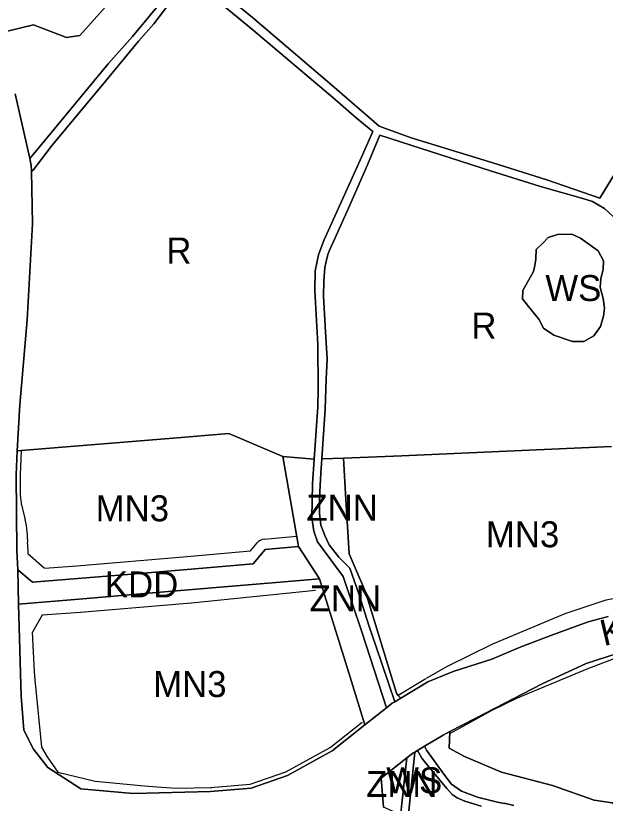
# Model space of a CAD drawing. Extents: x 7417187 to 7419415, y 5539178 to 5540826.
# Drawn here: x 7418228.7 to 7418455.5, y 5539930.4 to 5540233.3 of the extents above; entities that cross this region are included whole.
import ezdxf

# ---------------------------------------------------------------- set-up
doc = ezdxf.new("R2010")
doc.units = 0
for name, color, linetype in [('linie_rozgraniczajace', 7, 'Continuous'), ('linie_zabudowy_nieprzekraczalne', 7, 'Continuous'), ('oznaczenia_przeznaczen', 7, 'Continuous')]:
    doc.layers.add(name, color=color, linetype=linetype)

msp = doc.modelspace()

# ---------------------------------------------------------------- linework, layer by layer
at = {"layer": 'linie_rozgraniczajace'}
for p, q in [((7418228.49, 5540203.2), (7418234.02, 5540178.42)), ((7418234.02, 5540178.42), (7418234.62, 5540175.72)), ((7418234.62, 5540175.72), (7418234.67, 5540173.44)), ((7418234.67, 5540173.44), (7418235.17, 5540153.27)), ((7418235.17, 5540153.27), (7418233, 5540116.38)), ((7418233, 5540116.38), (7418230.22, 5540083.58)), ((7418230.22, 5540083.58), (7418229.26, 5540065.97)), ((7418229.26, 5540065.97), (7418228.84, 5540056.72)), ((7418228.84, 5540056.72), (7418229.08, 5540027.66)), ((7418229.08, 5540027.66), (7418229.44, 5540020.18)), ((7418229.44, 5540020.18), (7418229.69, 5540006.93)), ((7418229.69, 5540006.93), (7418230.69, 5539971.57)), ((7418448.84, 5540000.15), (7418456.65, 5540002.24)), ((7418434.59, 5539994.9), (7418448.84, 5540000.15)), ((7418422.7, 5539990.44), (7418434.59, 5539994.9)), ((7418411.84, 5539985.76), (7418422.7, 5539990.44)), ((7418396.96, 5539981.06), (7418411.84, 5539985.76)), ((7418460.09, 5539988), (7418448.1, 5539984.08)), ((7418448.1, 5539984.08), (7418431.16, 5539976.28)), ((7418387.18, 5539977.07), (7418396.96, 5539981.06)), ((7418376.77, 5539970.78), (7418387.18, 5539977.07)), ((7418431.16, 5539976.28), (7418405.44, 5539962.93)), ((7418230.69, 5539971.57), (7418231.83, 5539958.48)), ((7418374.56, 5539969.44), (7418376.77, 5539970.78)), ((7418362.93, 5539960.5), (7418371.35, 5539967.11)), ((7418371.35, 5539967.11), (7418373.55, 5539968.83)), ((7418373.55, 5539968.83), (7418374.56, 5539969.44)), ((7418405.44, 5539962.93), (7418395.62, 5539957.92)), ((7418231.83, 5539958.48), (7418235.49, 5539951.16)), ((7418350.41, 5539950.6), (7418362.93, 5539960.5)), ((7418395.62, 5539957.92), (7418393.1, 5539956.63)), ((7418393.1, 5539956.63), (7418385.93, 5539952.31)), ((7418385.93, 5539952.31), (7418383.29, 5539950.72)), ((7418235.49, 5539951.16), (7418241, 5539944.1)), ((7418333.18, 5539941.09), (7418350.41, 5539950.6)), ((7418381.45, 5539949.61), (7418379.12, 5539947.79)), ((7418382.19, 5539950.06), (7418381.45, 5539949.61)), ((7418383.29, 5539950.72), (7418382.19, 5539950.06)), ((7418379.12, 5539947.79), (7418369.25, 5539940)), ((7418241, 5539944.1), (7418253.73, 5539935.92)), ((7418319.22, 5539936.23), (7418333.18, 5539941.09)), ((7418369.25, 5539940), (7418370.12, 5539928.88)), ((7418253.73, 5539935.92), (7418270.91, 5539934.38)), ((7418270.91, 5539934.38), (7418274.03, 5539934.13)), ((7418274.03, 5539934.13), (7418303.62, 5539934.92)), ((7418303.62, 5539934.92), (7418319.22, 5539936.23))]:
    msp.add_line(p, q, dxfattribs=at)
for points in [[(7418227.82, 5540375.89), (7418237.98, 5540364.53), (7418262.36, 5540337.71), (7418286.86, 5540308.94), (7418290.2, 5540303.57), (7418291.35, 5540297.94), (7418292.32, 5540288.2), (7418294.69, 5540263.29), (7418294.79, 5540258.48), (7418294.26, 5540253.21), (7418292.47, 5540248.17), (7418273.58, 5540225.24), (7418264.17, 5540214.76), (7418235.51, 5540179.98), (7418234.02, 5540178.42), (7418228.49, 5540203.2)], [(7418226.81, 5540354.53), (7418253.06, 5540326.64), (7418254.07, 5540325.33), (7418267.85, 5540328.83), (7418275.05, 5540320.34), (7418284.84, 5540308.55), (7418288.35, 5540302.97), (7418275.62, 5540298.87), (7418279.2, 5540268.07), (7418279.82, 5540259.72), (7418279.51, 5540256.5), (7418279.22, 5540255.67), (7418269.71, 5540244.08), (7418253.27, 5540225.63), (7418248.19, 5540224.85), (7418235.5, 5540229.77), (7418221.14, 5540226.27)], [(7418221.14, 5540226.27), (7418235.5, 5540229.77), (7418248.19, 5540224.85), (7418253.27, 5540225.63), (7418269.71, 5540244.08), (7418279.22, 5540255.67), (7418279.51, 5540256.5), (7418279.82, 5540259.72), (7418279.2, 5540268.07), (7418275.62, 5540298.87), (7418288.35, 5540302.97), (7418284.84, 5540308.55), (7418275.05, 5540320.34), (7418267.85, 5540328.83), (7418254.07, 5540325.33), (7418253.06, 5540326.64), (7418226.81, 5540354.53)], [(7418297.74, 5540250.66), (7418319.78, 5540232.65), (7418350.22, 5540206.58), (7418368.55, 5540190.85), (7418369.92, 5540190.23), (7418380.76, 5540186.27), (7418412.2, 5540176.64), (7418433.02, 5540170.19), (7418453.39, 5540163.14), (7418465.08, 5540182.22)], [(7418538.04, 5540238.68), (7418496.96, 5540232.44), (7418486.08, 5540230.79), (7418462.63, 5540227.22), (7418464.94, 5540202.93), (7418468.97, 5540186.98), (7418465.08, 5540182.22), (7418453.39, 5540163.14), (7418433.02, 5540170.19), (7418412.2, 5540176.64), (7418380.76, 5540186.27), (7418369.92, 5540190.23), (7418368.55, 5540190.85), (7418350.22, 5540206.58), (7418319.78, 5540232.65), (7418297.74, 5540250.66)], [(7418458.58, 5540156.01), (7418455.21, 5540159.2), (7418450.6, 5540161.81), (7418446.87, 5540163), (7418430.5, 5540167.61), (7418411.37, 5540173.59), (7418368.73, 5540187.37), (7418363.97, 5540175.93), (7418357.14, 5540160.36), (7418351.56, 5540147.88), (7418349.51, 5540143.31), (7418348.8, 5540141.49), (7418348.05, 5540138.76), (7418347.62, 5540136.49), (7418347.16, 5540131.17), (7418347.09, 5540125.54), (7418347.66, 5540113.93), (7418348.47, 5540101.29), (7418348.1, 5540093.49), (7418347.74, 5540081.95), (7418346.45, 5540062.85), (7418346.08, 5540057.3), (7418345.55, 5540047.91), (7418345.55, 5540041.94), (7418346.1, 5540037.3), (7418346.99, 5540035.05), (7418347.58, 5540033.34), (7418349.25, 5540029.81), (7418353.02, 5540024.98), (7418357.16, 5540020.82), (7418360.48, 5540011.32), (7418364.66, 5539998.35), (7418367.22, 5539990.87), (7418374.56, 5539969.44), (7418373.55, 5539968.83), (7418371.35, 5539967.11), (7418361.82, 5539996.35), (7418354.7, 5540017.59), (7418344.81, 5540030.93), (7418343.3, 5540035), (7418342.62, 5540040.28), (7418342.81, 5540053.21), (7418343.51, 5540062.78), (7418344.85, 5540082.84), (7418345.06, 5540089.46), (7418344.87, 5540106.81), (7418343.78, 5540127.65), (7418343.91, 5540135.1), (7418345.13, 5540141.33), (7418347.17, 5540146.8), (7418361.24, 5540177.74), (7418366.05, 5540188.76), (7418359.69, 5540194.03), (7418350.67, 5540201.83), (7418319.98, 5540227.67), (7418295.39, 5540248.09), (7418281.73, 5540230.16), (7418275.85, 5540223.46), (7418262.63, 5540207.43), (7418242.72, 5540183.54), (7418235.31, 5540173.91), (7418234.67, 5540173.44), (7418234.62, 5540175.72), (7418234.02, 5540178.42), (7418235.51, 5540179.98), (7418264.17, 5540214.76), (7418273.58, 5540225.24), (7418292.47, 5540248.17)], [(7418457.92, 5540067.55), (7418377.24, 5540064.07), (7418354.81, 5540063.05), (7418346.45, 5540062.85), (7418347.74, 5540081.95), (7418348.1, 5540093.49), (7418348.47, 5540101.29), (7418347.66, 5540113.93), (7418347.09, 5540125.54), (7418347.16, 5540131.17), (7418347.62, 5540136.49), (7418348.05, 5540138.76), (7418348.8, 5540141.49), (7418349.51, 5540143.31), (7418351.56, 5540147.88), (7418357.14, 5540160.36), (7418363.97, 5540175.93), (7418368.73, 5540187.37), (7418411.37, 5540173.59), (7418430.5, 5540167.61), (7418446.87, 5540163), (7418450.6, 5540161.81), (7418455.21, 5540159.2), (7418458.58, 5540156.01)], [(7418456.65, 5540002.24), (7418448.84, 5540000.15), (7418434.59, 5539994.9), (7418422.7, 5539990.44), (7418411.84, 5539985.76), (7418396.96, 5539981.06), (7418387.18, 5539977.07), (7418376.77, 5539970.78), (7418375.8, 5539971.82), (7418375.17, 5539972.74), (7418363.2, 5540011.65), (7418359.25, 5540020.93), (7418356.89, 5540026.36), (7418355.7, 5540047.26), (7418354.81, 5540063.05), (7418377.24, 5540064.07), (7418457.92, 5540067.55)], [(7418467.69, 5539924.67), (7418458.16, 5539930.52), (7418451.22, 5539931.57), (7418435.2, 5539937.16), (7418415.61, 5539942.33), (7418401.3, 5539948.39), (7418395.47, 5539951.6), (7418395.62, 5539957.92), (7418405.44, 5539962.93), (7418431.16, 5539976.28), (7418448.1, 5539984.08), (7418460.09, 5539988), (7418469.7, 5539989.61), (7418477.67, 5539989.67), (7418486.12, 5539988.52), (7418526.66, 5539977.12), (7418549.91, 5539970.51), (7418571.39, 5539965.86), (7418582.99, 5539964.37), (7418587.53, 5539958.72), (7418610.13, 5539947.65), (7418632.89, 5539933.88), (7418645.61, 5539926.63)], [(7418420.25, 5539929.52), (7418416.54, 5539930.38), (7418416.54, 5539930.27), (7418414.01, 5539930.78), (7418406.38, 5539932.75), (7418400.14, 5539935.02), (7418396.28, 5539937.71), (7418393.8, 5539941.09), (7418386.7, 5539950.77), (7418385.93, 5539952.31), (7418393.1, 5539956.63), (7418395.62, 5539957.92), (7418395.47, 5539951.6), (7418401.3, 5539948.39), (7418415.61, 5539942.33), (7418435.2, 5539937.16), (7418451.22, 5539931.57), (7418458.16, 5539930.52), (7418467.69, 5539924.67)], [(7418407.77, 5539929.32), (7418401.48, 5539931.12), (7418398.49, 5539932.48), (7418396.55, 5539933.79), (7418394.54, 5539936.06), (7418391.34, 5539939.93), (7418386.41, 5539945.78), (7418384.87, 5539947.74), (7418383.73, 5539949.71), (7418383.29, 5539950.72), (7418385.93, 5539952.31), (7418386.7, 5539950.77), (7418393.8, 5539941.09), (7418396.28, 5539937.71), (7418400.14, 5539935.02), (7418406.38, 5539932.75), (7418414.01, 5539930.78), (7418416.54, 5539930.27), (7418416.54, 5539930.38), (7418420.25, 5539929.52)], [(7418379.52, 5539923.81), (7418382.19, 5539950.06), (7418383.29, 5539950.72), (7418383.73, 5539949.71), (7418384.87, 5539947.74), (7418386.41, 5539945.78), (7418391.34, 5539939.93), (7418394.54, 5539936.06), (7418396.55, 5539933.79), (7418398.49, 5539932.48), (7418401.48, 5539931.12), (7418407.77, 5539929.32)]]:
    msp.add_lwpolyline(points, dxfattribs=at)
for points in [[(7418343.51, 5540062.78), (7418331.42, 5540063.8), (7418310.69, 5540072.54), (7418289.27, 5540070.81), (7418229.26, 5540065.97), (7418230.22, 5540083.58), (7418233, 5540116.38), (7418235.17, 5540153.27), (7418234.67, 5540173.44), (7418235.31, 5540173.91), (7418242.72, 5540183.54), (7418262.63, 5540207.43), (7418275.85, 5540223.46), (7418281.73, 5540230.16), (7418295.39, 5540248.09), (7418319.98, 5540227.67), (7418350.67, 5540201.83), (7418359.69, 5540194.03), (7418366.05, 5540188.76), (7418361.24, 5540177.74), (7418347.17, 5540146.8), (7418345.13, 5540141.33), (7418343.91, 5540135.1), (7418343.78, 5540127.65), (7418344.87, 5540106.81), (7418345.06, 5540089.46), (7418344.85, 5540082.84)], [(7418447.21, 5540108.04), (7418442.92, 5540108.01), (7418435.7, 5540110.43), (7418431.68, 5540113.13), (7418429.93, 5540116.58), (7418425.93, 5540121.5), (7418423.67, 5540124.41), (7418423.82, 5540127.61), (7418427.81, 5540134.85), (7418428.42, 5540137.24), (7418428.8, 5540139.59), (7418428.93, 5540143.36), (7418431.64, 5540145.9), (7418433.55, 5540147.98), (7418437.07, 5540149.17), (7418442.6, 5540149.21), (7418445.93, 5540147.67), (7418452.75, 5540142.8), (7418454.81, 5540138.99), (7418454.65, 5540135.84), (7418453.76, 5540132.05), (7418453.46, 5540128.85), (7418454.68, 5540124.58), (7418455.16, 5540120.83), (7418454.77, 5540117.72), (7418453.63, 5540113.79), (7418451.03, 5540110.11)], [(7418447.21, 5540108.04), (7418451.03, 5540110.11), (7418453.63, 5540113.79), (7418454.77, 5540117.72), (7418455.16, 5540120.83), (7418454.68, 5540124.58), (7418453.46, 5540128.85), (7418453.76, 5540132.05), (7418454.65, 5540135.84), (7418454.81, 5540138.99), (7418452.75, 5540142.8), (7418445.93, 5540147.67), (7418442.6, 5540149.21), (7418437.07, 5540149.17), (7418433.55, 5540147.98), (7418431.64, 5540145.9), (7418428.93, 5540143.36), (7418428.8, 5540139.59), (7418428.42, 5540137.24), (7418427.81, 5540134.85), (7418423.82, 5540127.61), (7418423.67, 5540124.41), (7418425.93, 5540121.5), (7418429.93, 5540116.58), (7418431.68, 5540113.13), (7418435.7, 5540110.43), (7418442.92, 5540108.01)], [(7418331.42, 5540063.8), (7418337.5, 5540029.1), (7418324.57, 5540027.94), (7418320.05, 5540022.49), (7418294.56, 5540020.35), (7418273.14, 5540018.55), (7418235.1, 5540015.36), (7418229.44, 5540020.18), (7418229.08, 5540027.66), (7418228.84, 5540056.72), (7418229.26, 5540065.97), (7418289.27, 5540070.81), (7418310.69, 5540072.54)], [(7418343.51, 5540062.78), (7418342.81, 5540053.21), (7418342.62, 5540040.28), (7418343.3, 5540035), (7418344.81, 5540030.93), (7418354.7, 5540017.59), (7418361.82, 5539996.35), (7418371.35, 5539967.11), (7418362.93, 5539960.5), (7418357.32, 5539978.87), (7418345.57, 5540016.66), (7418337.5, 5540029.1), (7418331.42, 5540063.8)], [(7418376.77, 5539970.78), (7418374.56, 5539969.44), (7418367.22, 5539990.87), (7418364.66, 5539998.35), (7418360.48, 5540011.32), (7418357.16, 5540020.82), (7418353.02, 5540024.98), (7418349.25, 5540029.81), (7418347.58, 5540033.34), (7418346.99, 5540035.05), (7418346.1, 5540037.3), (7418345.55, 5540041.94), (7418345.55, 5540047.91), (7418346.08, 5540057.3), (7418346.45, 5540062.85), (7418354.81, 5540063.05), (7418355.7, 5540047.26), (7418356.89, 5540026.36), (7418359.25, 5540020.93), (7418363.2, 5540011.65), (7418375.17, 5539972.74), (7418375.8, 5539971.82)], [(7418345.57, 5540016.66), (7418325.74, 5540014.99), (7418278.17, 5540011), (7418254.5, 5540009.01), (7418229.69, 5540006.93), (7418229.44, 5540020.18), (7418235.1, 5540015.36), (7418273.14, 5540018.55), (7418294.56, 5540020.35), (7418320.05, 5540022.49), (7418324.57, 5540027.94), (7418337.5, 5540029.1)], [(7418362.93, 5539960.5), (7418350.41, 5539950.6), (7418333.18, 5539941.09), (7418319.22, 5539936.23), (7418303.62, 5539934.92), (7418274.03, 5539934.13), (7418270.91, 5539934.38), (7418253.73, 5539935.92), (7418241, 5539944.1), (7418235.49, 5539951.16), (7418231.83, 5539958.48), (7418230.69, 5539971.57), (7418229.69, 5540006.93), (7418254.5, 5540009.01), (7418278.17, 5540011), (7418325.74, 5540014.99), (7418345.57, 5540016.66), (7418357.32, 5539978.87)], [(7418379.52, 5539923.81), (7418376.67, 5539925.59), (7418379.12, 5539947.79), (7418381.45, 5539949.61), (7418382.19, 5539950.06)], [(7418376.67, 5539925.59), (7418374.72, 5539926.81), (7418370.12, 5539928.88), (7418369.25, 5539940), (7418379.12, 5539947.79)]]:
    msp.add_lwpolyline(points, close=True, dxfattribs=at)
at = {"layer": 'linie_zabudowy_nieprzekraczalne'}
for points in [[(7418230.77, 5540066.09), (7418230.34, 5540056.69), (7418230.4, 5540049.44)], [(7418231.12, 5540044.05), (7418232.32, 5540039.48)], [(7418324.22, 5540031.92), (7418336.81, 5540033.06)], [(7418233.24, 5540030.15), (7418233.27, 5540026.38)], [(7418318.97, 5540027.44), (7418321.5, 5540030.49)], [(7418233.27, 5540026.38), (7418239.56, 5540020.88)], [(7418239.75, 5540020.81), (7418252.12, 5540021.67), (7418294.56, 5540025.27), (7418318.97, 5540027.44)], [(7418344, 5540012.22), (7418296.32, 5540007.36)], [(7418412.18, 5539991.66), (7418440.04, 5540003.4), (7418455.81, 5540008.56), (7418469.64, 5540011.31)], [(7418296.15, 5540007.35), (7418253.56, 5540003.73)], [(7418253.47, 5540003.72), (7418238.92, 5540002.69)], [(7418238.9, 5540003.02), (7418235.05, 5539996.22)], [(7418235.02, 5539996.18), (7418235.79, 5539981), (7418236.15, 5539976.37)], [(7418394.51, 5539982.99), (7418412.18, 5539991.66)], [(7418638.78, 5539928.55), (7418626.03, 5539936.56), (7418606.61, 5539948.32), (7418586.21, 5539957.51), (7418573.41, 5539962.03), (7418548.93, 5539968.54), (7418516.48, 5539978.08), (7418495.35, 5539984.51), (7418484.59, 5539988.84), (7418473.66, 5539988.69), (7418461.51, 5539986.93), (7418448.39, 5539981.96), (7418421.59, 5539970.74), (7418411.52, 5539965.96)], [(7418386.69, 5539978.52), (7418394.51, 5539982.99)], [(7418236.13, 5539976.57), (7418238.59, 5539951.9)], [(7418375.8, 5539971.95), (7418386.4, 5539978.36)], [(7418411.52, 5539965.96), (7418398.31, 5539958.68)], [(7418303.6, 5539936.42), (7418318.91, 5539937.71), (7418332.57, 5539942.46), (7418349.58, 5539951.85), (7418361.92, 5539961.61), (7418361.92, 5539961.62)], [(7418398.31, 5539958.68), (7418395.6, 5539957.05)], [(7418238.59, 5539951.9), (7418240.74, 5539948.25)], [(7418240.71, 5539948.24), (7418244.83, 5539942.3), (7418259.18, 5539938.83), (7418276.8, 5539937.2)], [(7418276.7, 5539937.21), (7418284.76, 5539936.57)], [(7418284.76, 5539936.57), (7418290.33, 5539936.12), (7418304.08, 5539936.45)]]:
    msp.add_lwpolyline(points, dxfattribs=at)
for centre, radius, start, end in [((7418252.63, 5540049.67), 22.23, 180.5907, 194.429), ((7418195.5, 5540031.13), 37.75, 358.5122, 12.7629), ((7418324.57, 5540027.96), 3.98, 95.0222, 140.4428)]:
    msp.add_arc(centre, radius, start, end, dxfattribs=at)

# ---------------------------------------------------------------- texts
at = {"layer": 'oznaczenia_przeznaczen'}
for s, p in [('R', (7418286.6, 5540137.98)), ('WS', (7418432.43, 5540123.54)), ('R', (7418403.97, 5540109.1)), ('MN3', (7418259.42, 5540038.82)), ('ZNN', (7418340.49, 5540039.05)), ('MN3', (7418409.55, 5540028.84)), ('KDD', (7418262.96, 5540009.54)), ('ZNN', (7418341.72, 5540004.2)), ('MN3', (7418281.53, 5539971.22)), ('ZNN', (7418363.46, 5539932.79)), ('WS', (7418371.21, 5539934.23))]:
    msp.add_text(s, height=10, dxfattribs=at).set_placement(p)
msp.add_text('KDL', height=10, rotation=13.3009, dxfattribs=at).set_placement((7418454.9, 5539990.77))

doc.saveas('drawing.dxf')
